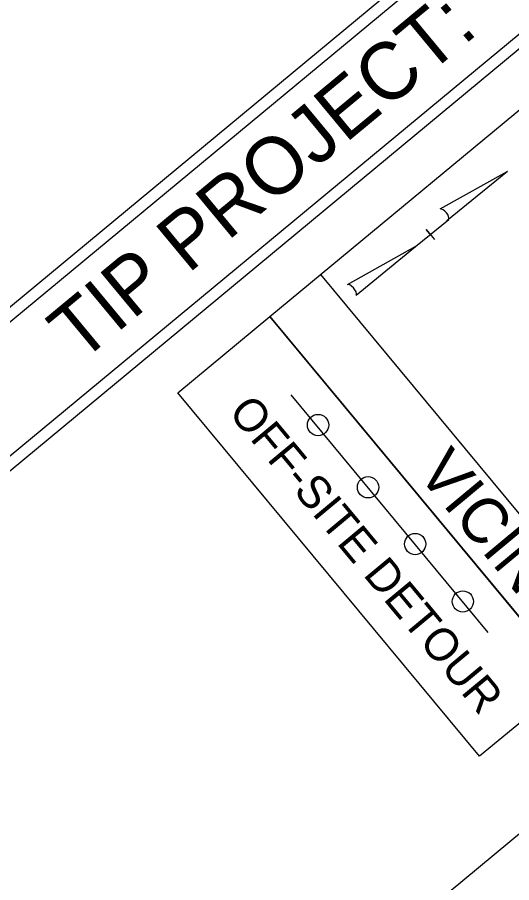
# Model space of a CAD drawing. Extents: x 2054826 to 2060231, y 685508 to 690809.
# Drawn here: x 2058198 to 2058522, y 689255 to 689821 of the extents above; entities that cross this region are included whole.
import ezdxf

# ---------------------------------------------------------------- set-up
doc = ezdxf.new("R2010")
doc.units = 0
for name, color, linetype in [('Default', 7, 'Continuous'), ('Old_Level_11', 7, 'Continuous'), ('Old_Level_21', 7, 'Continuous'), ('Prop North Arrow NAD83 for Plan Sheets CELL', 7, 'Continuous'), ('Sheet Title CELL', 7, 'Continuous')]:
    doc.layers.add(name, color=color, linetype=linetype)

msp = doc.modelspace()

# ---------------------------------------------------------------- linework, layer by layer
at = {"layer": 'Default'}
for p, q in [((2058303.06, 689575.56), (2058363.32, 689625.52)), ((2058363.32, 689625.52), (2058560.72, 689387.48)), ((2058500.46, 689337.51), (2058303.06, 689575.56)), ((2058560.72, 689387.48), (2058500.46, 689337.51))]:
    msp.add_line(p, q, dxfattribs=at)
msp.add_lwpolyline([(2058776.37, 689968.05), (2059134.67, 689535.97), (2058721.62, 689193.45), (2058363.32, 689625.52)], close=True, dxfattribs=at)
for centre in [(2058394.83, 689554.41), (2058427.55, 689513.67), (2058458.38, 689476.49), (2058489.58, 689438.88)]:
    msp.add_circle(centre, 6.96, dxfattribs=at)
at = {"layer": 'Old_Level_21'}
for p, q in [((2058396.35, 689652.92), (2058754.65, 689220.85)), ((2058376.92, 689574.27), (2058506.03, 689418.58))]:
    msp.add_line(p, q, dxfattribs=at)
msp.add_lwpolyline([(2058588.27, 689338), (2059498.4, 688240.46), (2058988.43, 687817.56), (2058078.29, 688915.11)], close=True, dxfattribs=at)
at = {"layer": 'Prop North Arrow NAD83 for Plan Sheets CELL'}
for p, q in [((2058474.79, 689695.93), (2058518.68, 689720.52)), ((2058518.71, 689720.48), (2058479.18, 689688.12)), ((2058518.71, 689720.48), (2058518.68, 689720.52)), ((2058518.71, 689720.48), (2058518.68, 689720.52)), ((2058458.67, 689671.33), (2058480.34, 689689.07)), ((2058479.18, 689688.12), (2058480.29, 689689.04)), ((2058465.55, 689682.5), (2058465.52, 689682.54)), ((2058467.96, 689679.56), (2058465.55, 689682.5)), ((2058465.59, 689682.45), (2058471, 689675.84)), ((2058458.67, 689671.33), (2058413.93, 689646.26)), ((2058419.79, 689639.45), (2058458.67, 689671.33))]:
    msp.add_line(p, q, dxfattribs=at)
for centre, start_param, end_param in [((2058477.18, 689692.17), 0.216388, 2.908219), ((2058416.67, 689642.64), 0.201328, 3.141593)]:
    msp.add_ellipse(centre, major_axis=(2.84, -3.52), ratio=0.461098, start_param=start_param, end_param=end_param, dxfattribs=at)
at = {"layer": 'Sheet Title CELL'}
for p, q in [((2057602.7, 689044.61), (2058780.44, 690021.25)), ((2057821.1, 689215.97), (2058785.23, 690015.48))]:
    msp.add_line(p, q, dxfattribs=at)
for points in [[(2058738.34, 690083.77), (2057549.05, 689097.55)], [(2058738.34, 690083.77), (2057549.05, 689097.55)], [(2058737.36, 690073.19), (2057559.61, 689096.57)]]:
    msp.add_lwpolyline(points, dxfattribs=at)

# ---------------------------------------------------------------- texts
at = {"layer": 'Old_Level_11'}
for s, height, p in [('OFF-SITE DETOUR ', 21.3625, (2058335.56, 689562.45)), ('VICINITY MAP', 29.6875, (2058458.94, 689522.81))]:
    msp.add_text(s, height=height, rotation=309.7424, dxfattribs=at).set_placement(p)
at = {"layer": 'Sheet Title CELL'}
msp.add_text('TIP PROJECT:', height=37.5, rotation=39.6672, dxfattribs=at).set_placement((2058238.96, 689594.42))

doc.saveas('drawing.dxf')
